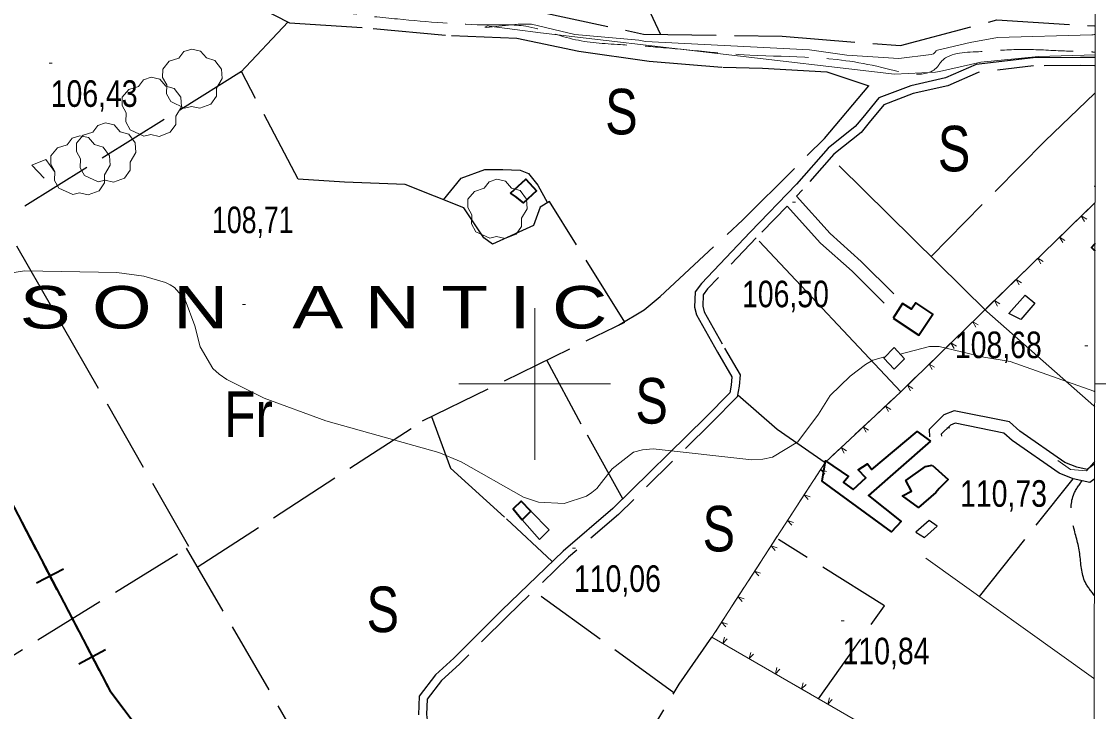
# Model space of a CAD drawing. Extents: x 483840 to 488445, y 4386047 to 4389027.
# Drawn here: x 487330.9 to 487685.7, y 4387892.1 to 4388119.4 of the extents above; entities that cross this region are included whole.
import ezdxf
from ezdxf.enums import TextEntityAlignment as Align

# ---------------------------------------------------------------- set-up
doc = ezdxf.new("R2010")
doc.units = 0
doc.header["$LTSCALE"] = 4
doc.linetypes.add('LONG_DASHED', pattern=[7.5, 6, -1.5])
doc.linetypes.add('MEDIUM_DASHED', pattern=[4.5, 3, -1.5])
for name, color, linetype, lineweight in [('1', 7, 'Continuous', 13), ('15', 7, 'LONG_DASHED', 13), ('21', 7, 'Continuous', 25), ('24', 7, 'Continuous', 13), ('25', 7, 'LONG_DASHED', 25), ('29', 7, 'Continuous', 13), ('34', 7, 'Continuous', 35), ('38', 7, 'Continuous', 25), ('47', 7, 'Continuous', 35), ('51', 7, 'Continuous', 13), ('7', 7, 'Continuous', 13), ('9', 7, 'Continuous', 13)]:
    doc.layers.add(name, color=color, linetype=linetype, lineweight=lineweight)
doc.layers.add('31', color=7, linetype='Continuous')
doc.layers.add('5', color=7, linetype='Continuous')

msp = doc.modelspace()

# ---------------------------------------------------------------- linework, layer by layer
at = {"layer": '1'}
for p, q in [((487500, 4388025), (487500, 4387975)), ((487475, 4388000), (487525, 4388000)), ((487684.53, 4388000), (487754.91, 4388000))]:
    msp.add_line(p, q, dxfattribs=at)
msp.add_lwpolyline([(484110.5, 4388760.3), (487685.8, 4388753.5), (487681.9, 4386441.2), (484105.5, 4386448.1)], close=True, dxfattribs=at)
at = {"layer": '15'}
msp.add_spline([(486893.89, 4388334.15), (486897.66, 4388326.32), (486901.59, 4388318.79), (486916.3, 4388301.6), (486931.17, 4388285), (486946.06, 4388266.23), (486961.18, 4388241.83), (486971.4, 4388222.35), (486976.88, 4388216.51), (486980.74, 4388214.98), (487014.75, 4388198.86), (487062.09, 4388181.42), (487106.44, 4388161.57), (487118.06, 4388158.42), (487129.84, 4388155.41), (487144.86, 4388153.07), (487183.1, 4388149.22), (487219.15, 4388147.67), (487249.69, 4388145.15), (487284.01, 4388143.35), (487309.63, 4388139.15), (487338.91, 4388136.81), (487373.52, 4388134.78), (487389.56, 4388131.36), (487412.81, 4388128.2), (487439.22, 4388122.11), (487454.85, 4388120.2), (487484.81, 4388118.29), (487497.1, 4388117.82), (487512.45, 4388113.59), (487528.23, 4388111.76), (487540.59, 4388110.91), (487570.91, 4388108.31), (487614.32, 4388104.25), (487633.02, 4388104.89), (487633.64, 4388105.77), (487646.19, 4388109.42), (487658.59, 4388110.15), (487671.71, 4388109.8), (487682.88, 4388109.36), (487684.71, 4388109.3)], degree=3, dxfattribs=at)
at = {"layer": '21'}
for points in [[(487661.57, 4388029.19), (487664.73, 4388026.63), (487660.16, 4388021.2), (487656.24, 4388023.25)], [(487615.04, 4388008.5), (487618.43, 4388012.01), (487621.86, 4388008.24), (487618.4, 4388004.88)], [(487625.62, 4387951.2), (487628.43, 4387949.4), (487632.65, 4387953.19), (487629.92, 4387954.99)]]:
    msp.add_lwpolyline(points, close=True, dxfattribs=at)
at = {"layer": '24'}
for p, q in [((487677.4, 4388052.71), (487682.78, 4388057.94)), ((487670.24, 4388045.74), (487675.62, 4388050.97)), ((487663.09, 4388038.77), (487668.46, 4388044.01)), ((487655.93, 4388031.8), (487661.3, 4388037.04)), ((487648.77, 4388024.84), (487654.14, 4388030.07)), ((487641.61, 4388017.87), (487646.99, 4388023.1)), ((487634.45, 4388010.9), (487639.83, 4388016.13)), ((487627.3, 4388003.93), (487632.67, 4388009.16)), ((487612.83, 4387990.15), (487618.31, 4387995.27)), ((487605.53, 4387983.33), (487611.01, 4387988.45)), ((487598.23, 4387976.51), (487603.71, 4387981.63)), ((487586.71, 4387960.29), (487590.79, 4387966.58)), ((487581.27, 4387951.91), (487585.35, 4387958.2)), ((487575.83, 4387943.53), (487579.91, 4387949.82)), ((487570.4, 4387935.15), (487574.48, 4387941.44)), ((487564.96, 4387926.77), (487569.04, 4387933.06)), ((487559.52, 4387918.39), (487563.6, 4387924.68)), ((487565.24, 4387912.69), (487558.74, 4387916.44)), ((487573.89, 4387907.69), (487567.39, 4387911.44)), ((487582.54, 4387902.69), (487576.05, 4387906.44)), ((487591.19, 4387897.7), (487584.7, 4387901.45)), ((487599.84, 4387892.7), (487593.35, 4387896.45))]:
    msp.add_line(p, q, dxfattribs=at)
for points in [[(487610.65, 4387886.46), (487558.39, 4387916.64), (487595.67, 4387974.11), (487620.63, 4387997.44), (487684.53, 4388059.65)], [(487681.87, 4388054.27), (487680.09, 4388055.33), (487681.1, 4388053.52)], [(487674.71, 4388047.3), (487672.93, 4388048.36), (487673.95, 4388046.56)], [(487667.56, 4388040.33), (487665.77, 4388041.39), (487666.79, 4388039.59)], [(487660.4, 4388033.36), (487658.62, 4388034.42), (487659.63, 4388032.62)], [(487653.24, 4388026.4), (487651.46, 4388027.45), (487652.47, 4388025.65)], [(487646.08, 4388019.43), (487644.3, 4388020.48), (487645.31, 4388018.68)], [(487638.92, 4388012.46), (487637.14, 4388013.51), (487638.16, 4388011.71)], [(487631.77, 4388005.49), (487629.98, 4388006.55), (487631, 4388004.74)], [(487620.13, 4387996.97), (487620.63, 4387997.44), (487625.51, 4388002.19)], [(487624.61, 4387998.52), (487622.82, 4387999.58), (487623.84, 4387997.77)], [(487617.33, 4387991.62), (487615.57, 4387992.71), (487616.55, 4387990.89)], [(487610.03, 4387984.8), (487608.27, 4387985.89), (487609.25, 4387984.07)], [(487602.73, 4387977.97), (487600.97, 4387979.07), (487601.95, 4387977.24)], [(487592.14, 4387968.67), (487595.67, 4387974.11), (487596.41, 4387974.81)], [(487596.16, 4387971.18), (487594.18, 4387971.82), (487595.57, 4387970.29)], [(487590.72, 4387962.8), (487588.75, 4387963.44), (487590.14, 4387961.9)], [(487585.28, 4387954.42), (487583.31, 4387955.06), (487584.7, 4387953.52)], [(487579.85, 4387946.04), (487577.87, 4387946.68), (487579.26, 4387945.14)], [(487574.41, 4387937.66), (487572.44, 4387938.29), (487573.83, 4387936.76)], [(487568.97, 4387929.28), (487567, 4387929.91), (487568.39, 4387928.38)], [(487563.54, 4387920.9), (487561.56, 4387921.53), (487562.95, 4387920)], [(487562.52, 4387916.56), (487561.99, 4387914.56), (487563.45, 4387916.03)], [(487571.17, 4387911.57), (487570.64, 4387909.56), (487572.1, 4387911.03)], [(487579.83, 4387906.57), (487579.29, 4387904.57), (487580.75, 4387906.04)], [(487588.48, 4387901.57), (487587.94, 4387899.57), (487589.4, 4387901.04)], [(487597.13, 4387896.58), (487596.6, 4387894.58), (487598.05, 4387896.04)]]:
    msp.add_lwpolyline(points, dxfattribs=at)
at = {"layer": '25'}
for p, q in [((487541.4, 4388115.15), (487515.3, 4388172.96)), ((487403.04, 4388102.61), (487418.76, 4388119.22)), ((487684.48, 4388117.93), (487684.73, 4388117.91)), ((487684.44, 4388095.69), (487684.69, 4388095.93)), ((487646.5, 4387930.04), (487677.44, 4387968.79)), ((487545.84, 4387898.29), (487499.66, 4387931.86))]:
    msp.add_line(p, q, dxfattribs=at)
for points in [[(487272.9, 4388138.73), (487307.47, 4388136.81), (487334.14, 4388135.21), (487359.25, 4388131.18), (487370.27, 4388130.89), (487385, 4388129.01), (487401.86, 4388125.41), (487409.4, 4388124.02), (487419.25, 4388118.96), (487446.74, 4388117.11), (487472.56, 4388114.71), (487494.15, 4388113.92), (487514.59, 4388109.64), (487537.69, 4388106.33), (487561.95, 4388104.35), (487575.07, 4388104), (487596.2, 4388102.85), (487610.13, 4388098.14)], [(487422.84, 4388133.51), (487431.67, 4388128.91), (487457.87, 4388123.95), (487500.61, 4388122.83), (487535.82, 4388115.23), (487581.5, 4388114.49), (487620.51, 4388111.44), (487652.24, 4388119.92), (487684.48, 4388117.93)], [(487388.85, 4387939.61), (487463.09, 4387987.86), (487529.74, 4388020.4), (487504.89, 4388060.07), (487501.85, 4388058.27), (487499.59, 4388052.18), (487486.15, 4388046.08), (487483.28, 4388048.18), (487476.63, 4388057.96), (487457.32, 4388065.67), (487437.38, 4388066.41), (487422.03, 4388067.49), (487403.45, 4388102.86), (487324.52, 4388053.94)], [(487527.65, 4388019.38), (487536.07, 4388024.37), (487541.37, 4388028.8), (487568.59, 4388054.05), (487595.47, 4388080.89), (487610.13, 4388098.14)], [(487630.63, 4388041.98), (487668.23, 4388080.11), (487684.44, 4388095.69)], [(487469.95, 4388060.63), (487475.76, 4388067.81), (487483.56, 4388070.61), (487489.49, 4388070.68), (487495.19, 4388070.45), (487497.93, 4388069.26), (487501.06, 4388065.42), (487504.19, 4388059.66)], [(487234.32, 4387852.55), (487386.08, 4387946.43), (487325.02, 4388053.07)], [(487529.01, 4387962.15), (487515.36, 4387986.72), (487503.97, 4388007.82)], [(487566.88, 4387996.38), (487579.91, 4387985.1), (487595.67, 4387974.11)], [(487466.01, 4387989.29), (487472.29, 4387972.24), (487490.68, 4387955.63), (487505.79, 4387941.49)], [(487593.53, 4387896.35), (487615.23, 4387926.93), (487580.37, 4387948.75)], [(487385.19, 4387945.88), (487453.81, 4387828.06), (487484.67, 4387780.21)], [(487477.77, 4387790.92), (487514.84, 4387846.35), (487547.56, 4387901.17), (487558.39, 4387916.64)]]:
    msp.add_lwpolyline(points, dxfattribs=at)
at = {"layer": '29'}
for points in [[(487384.64, 4388090.87), (487380.1, 4388092.99), (487378.69, 4388095.53), (487378.79, 4388098.51), (487377.42, 4388100.92), (487377.46, 4388103.67), (487379.62, 4388106.27), (487382.81, 4388107.27), (487384.46, 4388109.46), (487387.03, 4388110.29), (487389.89, 4388109.64), (487391.84, 4388107.37), (487394.65, 4388106.55), (487396.78, 4388103.7), (487397.02, 4388100.57), (487395.14, 4388097.42), (487395.14, 4388094.74), (487393.32, 4388092.13), (487389.7, 4388090.79), (487386.93, 4388091.42)], [(487371.27, 4388081.62), (487366.73, 4388083.74), (487365.32, 4388086.28), (487365.42, 4388089.26), (487364.05, 4388091.67), (487364.09, 4388094.42), (487366.25, 4388097.02), (487369.44, 4388098.02), (487371.09, 4388100.21), (487373.66, 4388101.04), (487376.52, 4388100.39), (487378.47, 4388098.12), (487381.28, 4388097.3), (487383.41, 4388094.45), (487383.65, 4388091.32), (487381.77, 4388088.17), (487381.77, 4388085.49), (487379.95, 4388082.88), (487376.33, 4388081.54), (487373.56, 4388082.17)], [(487356.24, 4388066.55), (487351.7, 4388068.67), (487350.29, 4388071.21), (487350.39, 4388074.19), (487349.02, 4388076.6), (487349.06, 4388079.35), (487351.22, 4388081.95), (487354.41, 4388082.95), (487356.06, 4388085.14), (487358.63, 4388085.97), (487361.49, 4388085.32), (487363.44, 4388083.05), (487366.25, 4388082.23), (487368.38, 4388079.38), (487368.62, 4388076.25), (487366.74, 4388073.1), (487366.74, 4388070.42), (487364.92, 4388067.81), (487361.3, 4388066.47), (487358.53, 4388067.1)], [(487347.8, 4388062.35), (487343.26, 4388064.47), (487341.85, 4388067.01), (487341.95, 4388069.99), (487340.58, 4388072.4), (487340.62, 4388075.15), (487342.78, 4388077.75), (487345.97, 4388078.75), (487347.62, 4388080.94), (487350.19, 4388081.77), (487353.05, 4388081.12), (487355, 4388078.85), (487357.81, 4388078.03), (487359.94, 4388075.18), (487360.18, 4388072.05), (487358.3, 4388068.9), (487358.3, 4388066.22), (487356.48, 4388063.61), (487352.86, 4388062.27), (487350.09, 4388062.9)], [(487485.18, 4388048.03), (487480.64, 4388050.15), (487479.23, 4388052.69), (487479.33, 4388055.67), (487477.96, 4388058.08), (487478, 4388060.83), (487480.16, 4388063.43), (487483.35, 4388064.43), (487485, 4388066.62), (487487.57, 4388067.45), (487490.43, 4388066.8), (487492.38, 4388064.53), (487495.19, 4388063.71), (487497.32, 4388060.86), (487497.56, 4388057.73), (487495.68, 4388054.58), (487495.68, 4388051.9), (487493.86, 4388049.29), (487490.24, 4388047.95), (487487.47, 4388048.58)]]:
    msp.add_lwpolyline(points, close=True, dxfattribs=at)
at = {"layer": '34'}
for p, q in [((487331.05, 4387954.37), (487335.68, 4387945.51)), ((487338, 4387941.09), (487342.63, 4387932.23)), ((487344.74, 4387938.97), (487335.88, 4387934.34)), ((487344.95, 4387927.8), (487349.58, 4387918.93)), ((487358.64, 4387912.4), (487349.78, 4387907.76)), ((487351.89, 4387914.51), (487356.52, 4387905.65))]:
    msp.add_line(p, q, dxfattribs=at)
for points in [[(486520.9, 4388755.72), (486603, 4388633), (486612, 4388581), (486746, 4388393), (486776, 4388338), (486812, 4388290), (486879, 4388250), (487017, 4388189), (487152, 4388148), (487234, 4388140), (487360, 4387899), (487497, 4387717), (487531, 4387660), (487608, 4387440), (487634, 4387181), (487675, 4387065), (487547, 4387001), (487350, 4386921), (487175, 4386900), (487110, 4386912), (487380, 4386493), (487280.6, 4386441.97)], [(487358.84, 4387901.22), (487360, 4387899), (487364.51, 4387893.01)]]:
    msp.add_lwpolyline(points, dxfattribs=at)
at = {"layer": '38'}
for p, q in [((487684.71, 4388107.5), (487684.46, 4388107.5)), ((487684.48, 4387973.68), (487684.24, 4387973.5)), ((487684.48, 4387968.73), (487684.24, 4387968.55))]:
    msp.add_line(p, q, dxfattribs=at)
at = {"layer": '38', "linetype": 'MEDIUM_DASHED'}
msp.add_line((487684.71, 4388104.82), (487684.46, 4388104.82), dxfattribs=at)
at = {"layer": '38'}
for points in [[(487684.46, 4388107.5), (487679.84, 4388107.53), (487664.19, 4388107.42), (487645.45, 4388105.22), (487635.3, 4388100.77), (487623.89, 4388098.21), (487613.41, 4388094.19), (487608.14, 4388087.81), (487605.63, 4388084.76), (487596.73, 4388077.63), (487586.31, 4388065.77), (487571.03, 4388049.97), (487554.93, 4388033.06), (487552.84, 4388030.33), (487552.71, 4388025.33), (487553.3, 4388022.73), (487560.21, 4388010.44), (487564.95, 4388002.33), (487564.73, 4387999.64), (487564.26, 4387997.03), (487556.38, 4387989.11), (487525.8, 4387958.99), (487509.37, 4387944.94), (487489.14, 4387925.45), (487473.34, 4387909.64), (487467.36, 4387904.19), (487461.95, 4387897.19), (487461.72, 4387891.05)], [(487618.28, 4388029.72), (487607.6, 4388040.36), (487597.34, 4388049.56), (487586.22, 4388061.81)], [(487615.14, 4388026.57), (487604.55, 4388037.13), (487594.2, 4388046.4), (487583.13, 4388058.61)], [(487684.24, 4387973.5), (487682.02, 4387971.82), (487678.58, 4387972.58), (487674.66, 4387974.1), (487659.8, 4387984.46), (487656.4, 4387987.48), (487638.21, 4387991.19), (487634.82, 4387989.83), (487629.92, 4387985.03), (487630.08, 4387982.58)], [(487684.24, 4387968.55), (487682.95, 4387967.58), (487677.44, 4387968.79), (487672.79, 4387970.59), (487657.35, 4387981.36), (487654.57, 4387983.83), (487638.58, 4387987.09), (487637.02, 4387986.47), (487633.97, 4387983.49), (487634.02, 4387982.85)]]:
    msp.add_lwpolyline(points, dxfattribs=at)
at = {"layer": '38', "linetype": 'MEDIUM_DASHED'}
for points in [[(487684.46, 4388104.82), (487679.84, 4388104.85), (487664.35, 4388104.74), (487646.16, 4388102.6), (487636.14, 4388098.21), (487624.67, 4388095.63), (487615.03, 4388091.93), (487610.21, 4388086.1), (487607.53, 4388082.84), (487598.6, 4388075.68), (487588.29, 4388063.95), (487586.22, 4388061.81)], [(487583.13, 4388058.61), (487572.97, 4388048.11), (487556.98, 4388031.32), (487555.51, 4388029.39), (487555.4, 4388025.59), (487555.83, 4388023.7), (487562.54, 4388011.78), (487567.69, 4388002.96), (487567.39, 4387999.29), (487566.76, 4387995.73), (487558.27, 4387987.21), (487527.61, 4387957.01), (487511.18, 4387942.95), (487491.02, 4387923.53), (487475.2, 4387907.7), (487469.34, 4387902.36), (487464.6, 4387896.23), (487464.41, 4387891.15), (487464.98, 4387885.89), (487465.35, 4387883.65)]]:
    msp.add_lwpolyline(points, dxfattribs=at)
at = {"layer": '38', "linetype": 'LONG_DASHED'}
for points in [[(487684.17, 4387930.6), (487681.18, 4387935.19), (487679.47, 4387944.76), (487677.25, 4387954.27), (487677.48, 4387963.35), (487680.41, 4387968.14)], [(487684.41, 4387930.23), (487684.35, 4387930.33), (487684.28, 4387930.42), (487684.17, 4387930.6)]]:
    msp.add_spline(points, degree=3, dxfattribs=at)
at = {"layer": '47'}
for p, q in [((487684.61, 4388046.25), (487684.36, 4388045.96)), ((487684.36, 4388044.1), (487684.6, 4388043.89))]:
    msp.add_line(p, q, dxfattribs=at)
for points in [[(487492.06, 4388062.81), (487497.06, 4388067.48), (487500.65, 4388063.63), (487496.34, 4388059.61), (487493.68, 4388061.71)], [(487618.09, 4388021.7), (487626.57, 4388016.07), (487631.17, 4388023.01), (487625.58, 4388026.69), (487624.19, 4388024.59), (487621.2, 4388026.55)], [(487630.46, 4387981.16), (487610.03, 4387963.31), (487620.76, 4387954.7), (487617.6, 4387951.26), (487594.77, 4387967.98), (487595.85, 4387974.63), (487603.44, 4387969.56), (487601.74, 4387967.58), (487604.91, 4387965.24), (487609.13, 4387969.03), (487606.58, 4387971.73), (487609.63, 4387973.67), (487611.08, 4387971.83), (487626.04, 4387984.35)], [(487631, 4387973.26), (487636.28, 4387968.55), (487633.27, 4387965.55), (487632.11, 4387964.23), (487626.43, 4387959.28), (487621.21, 4387963.17), (487624.1, 4387964.74), (487622.24, 4387968.17), (487628.74, 4387972.8)], [(487495.85, 4387955.26), (487498.78, 4387958.11), (487495.56, 4387961.41), (487492.94, 4387958.87)]]:
    msp.add_lwpolyline(points, close=True, dxfattribs=at)
for points in [[(487684.64, 4388065.18), (487684.59, 4388065.14), (487684.64, 4388065.08)], [(487684.36, 4388045.96), (487683.44, 4388044.9), (487684.36, 4388044.1)]]:
    msp.add_lwpolyline(points, dxfattribs=at)
at = {"layer": '51'}
for p, q in [((487620.63, 4387997.44), (487573.96, 4388047.08)), ((487684.52, 4387992.63), (487684.27, 4387992.85)), ((487684.49, 4387974.45), (487684.24, 4387974.17)), ((487628.92, 4387942.63), (487684.13, 4387903.08)), ((487684.13, 4387903.08), (487684.37, 4387902.91))]:
    msp.add_line(p, q, dxfattribs=at)
for points in [[(487341.81, 4388069.96), (487338.92, 4388073.94), (487334.37, 4388072.03), (487338.38, 4388067.8)], [(487684.27, 4387992.85), (487648.98, 4388023.89), (487600.34, 4388071.83)], [(487684.24, 4387974.17), (487681.82, 4387971.41), (487676.58, 4387971.85), (487672.31, 4387974.81)], [(487498.78, 4387958.11), (487504.77, 4387951.96), (487501.61, 4387948.74), (487495.85, 4387955.26)]]:
    msp.add_lwpolyline(points, dxfattribs=at)
at = {"layer": '7'}
for p, q in [((487340.07, 4388105.63), (487341.07, 4388105.63)), ((487584.9, 4388059.84), (487585.9, 4388059.84)), ((487403.72, 4388026.16), (487404.72, 4388026.16)), ((487681.27, 4388012.53), (487682.27, 4388012.53)), ((487635.77, 4387985.58), (487636.77, 4387985.58)), ((487512.44, 4387945.89), (487513.44, 4387945.89)), ((487600.95, 4387922.04), (487601.95, 4387922.04))]:
    msp.add_line(p, q, dxfattribs=at)
at = {"layer": '9'}
for points in [[(487684.72, 4388115.1), (487684.36, 4388115.14), (487683.99, 4388115.01), (487683.58, 4388115.01), (487652.49, 4388114.09), (487643.47, 4388112.49), (487632.73, 4388109.89), (487632.46, 4388109.79), (487632.25, 4388109.69), (487631.93, 4388109.23), (487631.39, 4388108.74), (487630.6, 4388108.47), (487619.94, 4388107.23), (487602.88, 4388108.27), (487590.55, 4388110.04), (487536.47, 4388112.84), (487534.3, 4388113.18), (487513.28, 4388115.13), (487498.94, 4388118.51), (487494.52, 4388118.48), (487484.01, 4388117.39), (487483.57, 4388117.55), (487484.28, 4388117.82)], [(487484.28, 4388117.82), (487484.59, 4388117.9), (487484.97, 4388117.89), (487501.91, 4388115.63), (487618.56, 4388102.05), (487632.03, 4388102.64), (487633.36, 4388102.86), (487646.96, 4388106), (487665.98, 4388107.84), (487684.71, 4388108.4)], [(487327.08, 4388036.52), (487331.91, 4388037.3), (487362.39, 4388036.66), (487371.29, 4388035.5), (487378.38, 4388033.45), (487379.94, 4388032.66), (487381.32, 4388031.77), (487384.81, 4388027.71), (487388.09, 4388019.11), (487389.82, 4388012.2), (487394.01, 4388005.09), (487396.09, 4388003.24), (487398.57, 4388001.44), (487410.85, 4387995.36), (487431.16, 4387987.82), (487468.48, 4387977.43), (487475.73, 4387974.35), (487496.29, 4387962.67), (487501.26, 4387961.08), (487509.73, 4387960.63), (487517.11, 4387963.06), (487518.87, 4387964.2), (487520.52, 4387965.54), (487525.49, 4387972.06), (487532.57, 4387977.57), (487535.56, 4387978.26), (487538.99, 4387978.6), (487571.49, 4387974.97), (487575.12, 4387975.25), (487578.35, 4387975.87), (487586.73, 4387980.98), (487593.47, 4387990.04), (487597.31, 4387996.22), (487603.9, 4388002.55), (487609.04, 4388006.44), (487611.43, 4388007.8), (487614.93, 4388008.81), (487615.4, 4388008.87)], [(487620.44, 4388009.81), (487630.12, 4388012.35), (487633.27, 4388012.31), (487648.03, 4388008.8), (487656.63, 4388007.43), (487684.27, 4387997.61), (487684.52, 4387997.45)]]:
    msp.add_lwpolyline(points, dxfattribs=at)

# ---------------------------------------------------------------- texts
at = {"layer": '31'}
for s, width, p in [('S', 0.8, (487528.58, 4388082.2)), ('S', 0.8, (487638.17, 4388070.02)), ('S', 0.8, (487538.53, 4387986.95)), ('Fr', 0.85, (487405.68, 4387982.52)), ('S', 0.8, (487560.67, 4387944.86)), ('S', 0.8, (487449.97, 4387918.27))]:
    msp.add_text(s, height=15, dxfattribs=dict(at, width=width)).set_placement(p, align=Align.CENTER)
at = {"layer": '5', "width": 1.35}
msp.add_text('S O N   A N T I C', height=13.99, dxfattribs=at).set_placement((487523.95, 4388018.27), align=Align.RIGHT)
at = {"layer": '7'}
for s, width, p in [('106,43', 0.8, (487340.57, 4388091.26)), ('108,71', 0.75, (487393.72, 4388049.67)), ('106,50', 0.8, (487568.31, 4388025.26)), ('108,68', 0.8, (487638.44, 4388008.51)), ('110,73', 0.8, (487640.15, 4387959.55)), ('110,06', 0.8, (487512.94, 4387931.52)), ('110,84', 0.8, (487601.45, 4387907.67))]:
    msp.add_text(s, height=8.75, dxfattribs=dict(at, width=width)).set_placement(p)

doc.saveas('drawing.dxf')
